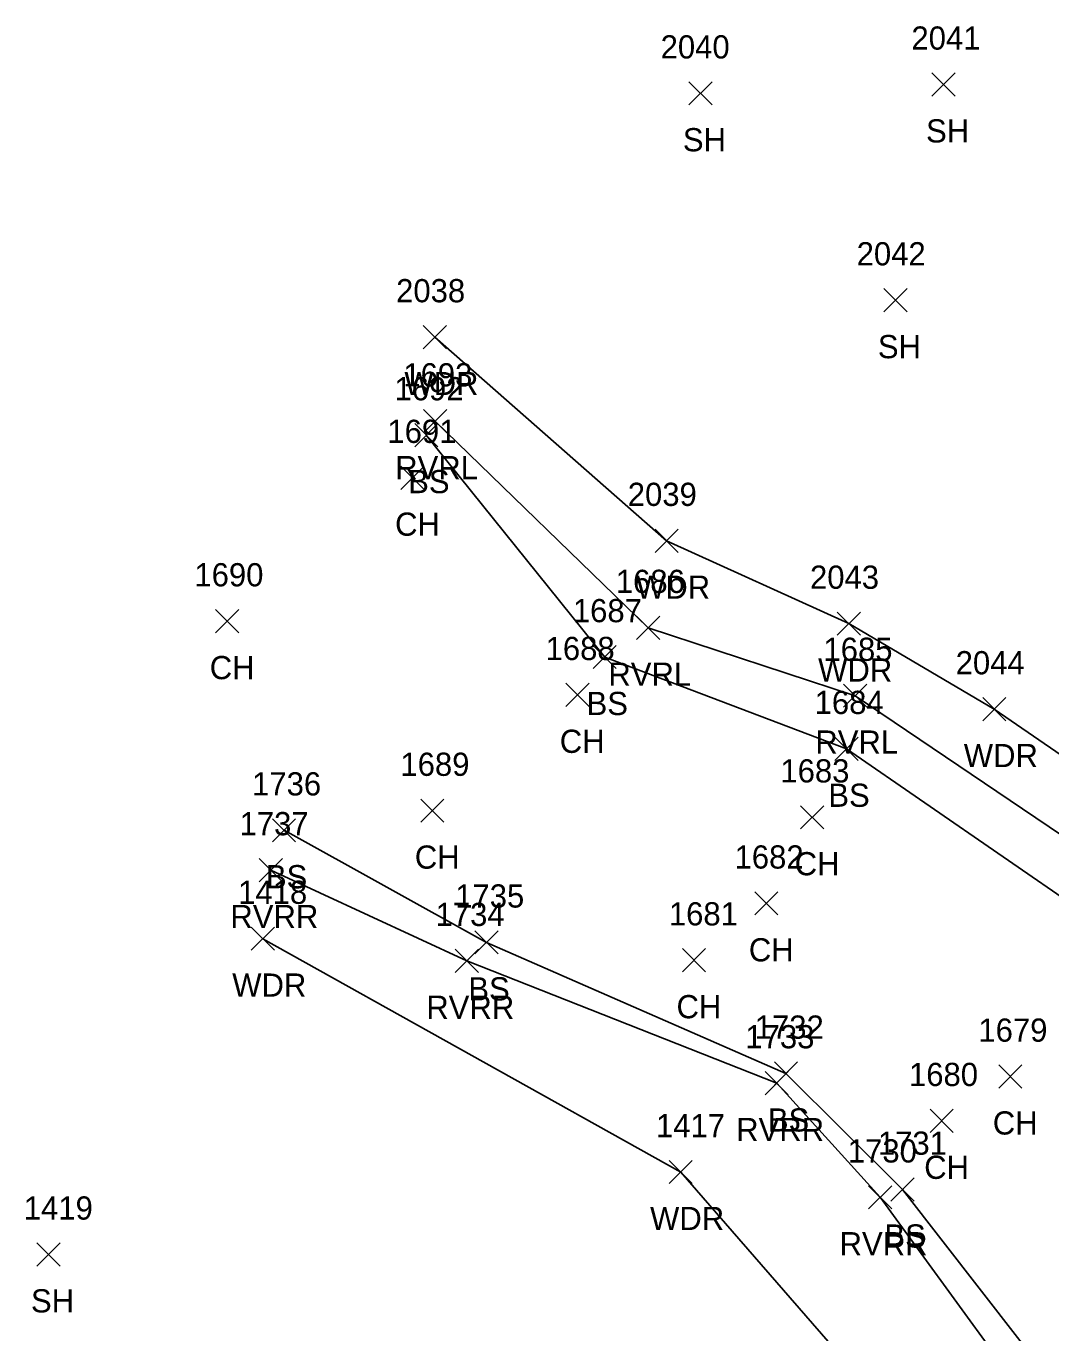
# Model space of a CAD drawing. Extents: x 1653908 to 1654393, y 539913 to 544256.
# Drawn here: x 1653908.2 to 1653996.5, y 541690.6 to 541803.2 of the extents above; entities that cross this region are included whole.
import ezdxf

# ---------------------------------------------------------------- set-up
doc = ezdxf.new("R2010")
doc.units = 0
for name, color, linetype in [('L_A', 7, 'Continuous'), ('L_I', 7, 'Continuous'), ('L_TIC', 7, 'Continuous'), ('LAWA', 7, 'Continuous'), ('LAWE', 7, 'Continuous'), ('LELB', 7, 'Continuous')]:
    doc.layers.add(name, color=color, linetype=linetype)

msp = doc.modelspace()

# ---------------------------------------------------------------- linework, layer by layer
at = {"layer": 'L_TIC'}
for points in [[(1653965.34, 541796.41), (1653967.34, 541798.41)], [(1653967.34, 541796.41), (1653965.34, 541798.41)], [(1653986.29, 541797.17), (1653988.29, 541799.17)], [(1653988.29, 541797.17), (1653986.29, 541799.17)], [(1653982.14, 541778.58), (1653984.14, 541780.58)], [(1653984.14, 541778.58), (1653982.14, 541780.58)], [(1653942.46, 541775.4), (1653944.46, 541777.4)], [(1653944.46, 541775.4), (1653942.46, 541777.4)], [(1653942.48, 541768.15), (1653944.48, 541770.15)], [(1653944.48, 541768.15), (1653942.48, 541770.15)], [(1653941.72, 541766.95), (1653943.72, 541768.95)], [(1653943.72, 541766.95), (1653941.72, 541768.95)], [(1653940.54, 541763.28), (1653942.54, 541765.28)], [(1653942.54, 541763.28), (1653940.54, 541765.28)], [(1653962.43, 541757.85), (1653964.43, 541759.85)], [(1653964.43, 541757.85), (1653962.43, 541759.85)], [(1653924.57, 541750.92), (1653926.57, 541752.92)], [(1653926.57, 541750.92), (1653924.57, 541752.92)], [(1653960.84, 541750.35), (1653962.84, 541752.35)], [(1653962.84, 541750.35), (1653960.84, 541752.35)], [(1653978.12, 541750.71), (1653980.12, 541752.71)], [(1653980.12, 541750.71), (1653978.12, 541752.71)], [(1653957.09, 541747.83), (1653959.09, 541749.83)], [(1653959.09, 541747.83), (1653957.09, 541749.83)], [(1653954.74, 541744.57), (1653956.74, 541746.57)], [(1653956.74, 541744.57), (1653954.74, 541746.57)], [(1653978.68, 541744.5), (1653980.68, 541746.5)], [(1653980.68, 541744.5), (1653978.68, 541746.5)], [(1653990.66, 541743.34), (1653992.66, 541745.34)], [(1653992.66, 541743.34), (1653990.66, 541745.34)], [(1653977.92, 541739.92), (1653979.92, 541741.92)], [(1653979.92, 541739.92), (1653977.92, 541741.92)], [(1653942.24, 541734.59), (1653944.24, 541736.59)], [(1653944.24, 541734.59), (1653942.24, 541736.59)], [(1653974.97, 541734.02), (1653976.97, 541736.02)], [(1653976.97, 541734.02), (1653974.97, 541736.02)], [(1653929.46, 541732.9), (1653931.46, 541734.9)], [(1653931.46, 541732.9), (1653929.46, 541734.9)], [(1653928.33, 541729.47), (1653930.33, 541731.47)], [(1653930.33, 541729.47), (1653928.33, 541731.47)], [(1653971.02, 541726.6), (1653973.02, 541728.6)], [(1653973.02, 541726.6), (1653971.02, 541728.6)], [(1653927.64, 541723.56), (1653929.64, 541725.56)], [(1653929.64, 541723.56), (1653927.64, 541725.56)], [(1653946.9, 541723.24), (1653948.9, 541725.24)], [(1653948.9, 541723.24), (1653946.9, 541725.24)], [(1653945.21, 541721.65), (1653947.21, 541723.65)], [(1653947.21, 541721.65), (1653945.21, 541723.65)], [(1653964.79, 541721.7), (1653966.79, 541723.7)], [(1653966.79, 541721.7), (1653964.79, 541723.7)], [(1653972.71, 541711.94), (1653974.71, 541713.94)], [(1653974.71, 541711.94), (1653972.71, 541713.94)], [(1653971.91, 541711.11), (1653973.91, 541713.11)], [(1653973.91, 541711.11), (1653971.91, 541713.11)], [(1653992.04, 541711.68), (1653994.04, 541713.68)], [(1653994.04, 541711.68), (1653992.04, 541713.68)], [(1653986.13, 541707.86), (1653988.13, 541709.86)], [(1653988.13, 541707.86), (1653986.13, 541709.86)], [(1653963.64, 541703.45), (1653965.64, 541705.45)], [(1653965.64, 541703.45), (1653963.64, 541705.45)], [(1653982.75, 541701.94), (1653984.75, 541703.94)], [(1653984.75, 541701.94), (1653982.75, 541703.94)], [(1653980.82, 541701.27), (1653982.82, 541703.27)], [(1653982.82, 541701.27), (1653980.82, 541703.27)], [(1653909.17, 541696.35), (1653911.17, 541698.35)], [(1653911.17, 541696.35), (1653909.17, 541698.35)]]:
    msp.add_lwpolyline(points, dxfattribs=at)
at = {"layer": 'LAWA'}
for points in [[(1653943.46, 541776.4), (1653963.43, 541758.85), (1653979.12, 541751.71), (1653991.66, 541744.34), (1654013.82, 541729.11), (1654015.81, 541726.17), (1654025.6, 541714.63), (1654043.62, 541700.09), (1654049.6, 541695.91), (1654052.07, 541692.32)], [(1654038.91, 541618.25), (1654026.28, 541639.03), (1654008.01, 541653.16), (1653988.11, 541677.48), (1653964.64, 541704.45), (1653928.64, 541724.56)]]:
    msp.add_lwpolyline(points, dxfattribs=at)
at = {"layer": 'LAWE'}
for points in [[(1654199.26, 541471.36), (1654181.86, 541503.28), (1654178.82, 541509.62), (1654164.46, 541535.09), (1654153.73, 541550.44), (1654126.86, 541584.5), (1654110.11, 541605.8), (1654090.45, 541629.39), (1654082.44, 541647.34), (1654069.57, 541661.67), (1654051.08, 541684.15), (1654038.47, 541696.15), (1654026.73, 541704.45), (1654010.8, 541724.45), (1653979.68, 541745.5), (1653961.84, 541751.35), (1653943.48, 541769.15)], [(1654165.75, 541453.3), (1654145.37, 541485.64), (1654128.33, 541517.88), (1654118.98, 541538.06), (1654102.88, 541558.43), (1654087.64, 541571.29), (1654080.69, 541574.23), (1654068.7, 541590.65), (1654047.98, 541616.51), (1654043.58, 541623.07), (1654031.27, 541642.94), (1654001.65, 541675.05), (1653981.82, 541702.27), (1653972.91, 541712.11), (1653946.21, 541722.65), (1653929.33, 541730.47)]]:
    msp.add_lwpolyline(points, dxfattribs=at)
at = {"layer": 'LELB'}
for points in [[(1654033.73, 541691.91), (1654024.04, 541702.16), (1654005.92, 541722.3), (1653978.92, 541740.92), (1653958.09, 541748.83), (1653942.72, 541767.95)], [(1654046.04, 541625.31), (1654032.71, 541643.47), (1654003.97, 541676.92), (1653983.75, 541702.94), (1653973.71, 541712.94), (1653947.9, 541724.24), (1653930.46, 541733.9)]]:
    msp.add_lwpolyline(points, dxfattribs=at)

# ---------------------------------------------------------------- texts
at = {"layer": 'L_A'}
for s, p in [('SH', (1653985.78, 541793.17)), ('SH', (1653964.83, 541792.41)), ('SH', (1653981.63, 541774.58)), ('WDR', (1653940.83, 541771.4)), ('RVRL', (1653940.04, 541764.15)), ('BS', (1653941.16, 541762.95)), ('CH', (1653940.03, 541759.28)), ('WDR', (1653960.79, 541753.85)), ('CH', (1653924.06, 541746.92)), ('RVRL', (1653958.41, 541746.35)), ('WDR', (1653976.48, 541746.71)), ('BS', (1653956.53, 541743.83)), ('CH', (1653954.22, 541740.57)), ('RVRL', (1653976.24, 541740.5)), ('WDR', (1653989.03, 541739.34)), ('BS', (1653977.36, 541735.92)), ('CH', (1653941.73, 541730.59)), ('CH', (1653974.46, 541730.02)), ('BS', (1653928.9, 541728.9)), ('RVRR', (1653925.84, 541725.47)), ('CH', (1653970.51, 541722.6)), ('WDR', (1653926, 541719.56)), ('BS', (1653946.34, 541719.24)), ('RVRR', (1653942.72, 541717.65)), ('CH', (1653964.28, 541717.7)), ('BS', (1653972.15, 541707.94)), ('CH', (1653991.53, 541707.68)), ('RVRR', (1653969.42, 541707.11)), ('CH', (1653985.62, 541703.86)), ('WDR', (1653962, 541699.45)), ('RVRR', (1653978.33, 541697.27)), ('BS', (1653982.19, 541697.94)), ('SH', (1653908.66, 541692.35))]:
    msp.add_text(s, height=2, dxfattribs=at).set_placement(p)
at = {"layer": 'L_I'}
for s, p in [('2041', (1653984.52, 541801.17)), ('2040', (1653962.91, 541800.41)), ('2042', (1653979.8, 541782.58)), ('2038', (1653940.12, 541779.4)), ('1693', (1653940.74, 541772.15)), ('1692', (1653939.98, 541770.95)), ('1691', (1653939.37, 541767.28)), ('2039', (1653960.08, 541761.85)), ('1690', (1653922.74, 541754.92)), ('2043', (1653975.78, 541754.71)), ('1686', (1653959.05, 541754.35)), ('1687', (1653955.35, 541751.83)), ('1688', (1653953, 541748.57)), ('1685', (1653976.94, 541748.5)), ('2044', (1653988.33, 541747.34)), ('1684', (1653976.18, 541743.92)), ('1689', (1653940.49, 541738.59)), ('1683', (1653973.23, 541738.02)), ('1736', (1653927.71, 541736.9)), ('1737', (1653926.63, 541733.47)), ('1682', (1653969.28, 541730.6)), ('1418', (1653926.51, 541727.56)), ('1735', (1653945.21, 541727.24)), ('1734', (1653943.52, 541725.65)), ('1681', (1653963.62, 541725.7)), ('1732', (1653971.02, 541715.94)), ('1679', (1653990.29, 541715.68)), ('1733', (1653970.21, 541715.11)), ('1680', (1653984.31, 541711.86)), ('1417', (1653962.51, 541707.45)), ('1730', (1653979.04, 541705.27)), ('1731', (1653981.63, 541705.94)), ('1419', (1653908.04, 541700.35))]:
    msp.add_text(s, height=2, dxfattribs=at).set_placement(p)

doc.saveas('drawing.dxf')
